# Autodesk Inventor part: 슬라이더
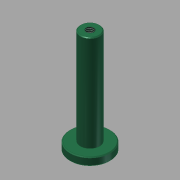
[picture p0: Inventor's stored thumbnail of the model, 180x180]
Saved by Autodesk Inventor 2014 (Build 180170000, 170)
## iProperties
Created: 2016-02
Part Number: 슬라이더
Material: 스테인리스강
Document SubType Name: Modeling
Designer: mduedu
Density: 8.08 g/cm^3
Appearance: 매끄러움 - 짙은 바다 녹색
Mass: 72.5507 g
Surface Area: 37.669 cm^2
Volume: 8.97904 cm^3
Author: mduedu
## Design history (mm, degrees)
sketch "스케치1"
  geometry: C1 r 12.5 at (0, 0); 1 further point
  constraints: 1 centre point, 1 coincident
  dimensions: "d0" = 25 diameter of C1
extrude "돌출1" new body sketch "스케치1" distance "d1" = 5; taper "d2" = 0 deg
sketch "스케치2"
  geometry: C1 r 6 at (0, 0); 1 further point
  constraints: 1 centre point, 1 coincident
  dimensions: "d3" = 12 diameter of C1
extrude "돌출2" join sketch "스케치2" distance "d4" = 60; taper "d5" = 0 deg
chamfer "모따기1" distance "d6" = 0.5; stored, may be unused: second distance "d7" = 2, angle "d8" = 45 deg
hole "구멍1" diameter "d11" = 4.917; stored, may be unused: countersink angle "d15" = 90 deg, drill point angle "d17" = 118 deg; dims "d9" = 10, "d10" = 10, "d12" = 10, "d13" = 4, "d14" = 2, "d16" = 12
chamfer "모따기2" distance "d18" = 0.5; stored, may be unused: second distance "d19" = 2, angle "d20" = 45 deg
node "솔리드1"
